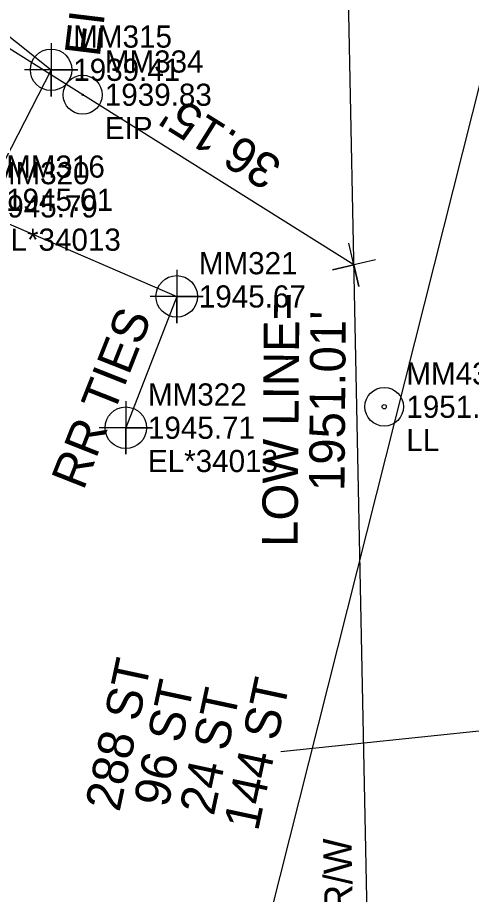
# Model space of a CAD drawing. Extents: x 1004514 to 1005247, y 553695 to 554706.
# Drawn here: x 1004934 to 1004985.3, y 554027.6 to 554126.5 of the extents above; entities that cross this region are included whole.
import ezdxf

# ---------------------------------------------------------------- set-up
doc = ezdxf.new("R2010")
doc.units = 0
for name, color, linetype in [('Default Symbol Cogo Comment', 7, 'Continuous'), ('Default Symbol Cogo Elevation', 7, 'Continuous'), ('Default Symbol Cogo Number', 7, 'Continuous'), ('Exist Building', 7, 'Continuous'), ('Exist Building Cogo Elevation', 7, 'Continuous'), ('Exist Building Cogo Number', 7, 'Continuous'), ('Exist Building Cogo Point CELL', 7, 'Continuous'), ('Exist Building Text', 7, 'Continuous'), ('Exist Property Corner CELL', 7, 'Continuous'), ('Exist Property Iron Pin CELL', 7, 'Continuous'), ('Exist Property Iron Pin Cogo Comment', 7, 'Continuous'), ('Exist Property Iron Pin Cogo Elevation', 7, 'Continuous'), ('Exist Property Iron Pin Cogo Number', 7, 'Continuous'), ('Exist Property Iron Pin Text', 7, 'Continuous'), ('Exist Property Line', 7, 'Continuous'), ('Exist Property Line Text', 7, 'Continuous'), ('Exist Right of Way Line', 7, 'Continuous'), ('Exist Right of Way Line Text', 7, 'Continuous'), ('Exist Utilities Other Located Object CELL', 7, 'Continuous'), ('Exist Utilities Other Located Object Text', 7, 'Continuous'), ('Exist Utilities Telephone UG Conduit SUE LOS B Leader', 7, 'Continuous'), ('Exist Utilities Telephone UG Conduit SUE LOS B Text', 7, 'Continuous'), ('Exist Vegetation Woods Line', 7, 'Continuous'), ('Exist Vegetation Woods Line Cogo Elevation', 7, 'Continuous'), ('Exist Vegetation Woods Line Cogo Number', 7, 'Continuous'), ('Exist Vegetation Woods Line Cogo Point CELL', 7, 'Continuous'), ('Scratch_Level_3', 7, 'Continuous')]:
    doc.layers.add(name, color=color, linetype=linetype)

msp = doc.modelspace()

# ---------------------------------------------------------------- linework, layer by layer
at = {"layer": 'Exist Building'}
msp.add_lwpolyline([(1004928.515, 554105.229), (1004952.008, 554095.071), (1004946.261, 554080.257)], dxfattribs=at)
at = {"layer": 'Exist Building Cogo Point CELL'}
for points in [[(1004952.008, 554098.071), (1004952.008, 554092.071), (1004952.008, 554095.071), (1004955.008, 554095.071), (1004949.008, 554095.071)], [(1004946.261, 554083.257), (1004946.261, 554077.257), (1004946.261, 554080.257), (1004949.261, 554080.257), (1004943.261, 554080.257)]]:
    msp.add_lwpolyline(points, dxfattribs=at)
for centre in [(1004952.008, 554095.071), (1004946.261, 554080.257)]:
    msp.add_circle(centre, 2.344, dxfattribs=at)
at = {"layer": 'Exist Property Corner CELL'}
msp.add_line((1004972.021, 554098.632), (1004972.021, 554098.632), dxfattribs=at)
msp.add_lwpolyline([(1004974.458, 554099.191), (1004969.584, 554098.072), (1004972.021, 554098.632), (1004972.58, 554096.195), (1004971.462, 554101.068)], dxfattribs=at)
at = {"layer": 'Exist Property Iron Pin CELL'}
for radius in [2.203, 0.0707]:
    msp.add_circle((1004941.389, 554117.826), radius, dxfattribs=at)
at = {"layer": 'Exist Property Line'}
for p, q in [((1004941.389, 554117.826), (1004781.385, 554218.083)), ((1004972.021, 554098.632), (1004941.389, 554117.826))]:
    msp.add_line(p, q, dxfattribs=at)
at = {"layer": 'Exist Right of Way Line'}
msp.add_line((1004974.633, 553969.453), (1004971.246, 554136.929), dxfattribs=at)
at = {"layer": 'Exist Utilities Other Located Object CELL'}
for radius in [2.18, 0.24]:
    msp.add_circle((1004975.438, 554082.623), radius, dxfattribs=at)
at = {"layer": 'Exist Utilities Telephone UG Conduit SUE LOS B Leader'}
msp.add_line((1004992.647, 554046.707), (1004963.772, 554043.71), dxfattribs=at)
at = {"layer": 'Exist Vegetation Woods Line'}
msp.add_lwpolyline([(1004918.605, 554135.996), (1004937.826, 554120.641), (1004930.248, 554105.974), (1004908.277, 554113.327)], dxfattribs=at)
at = {"layer": 'Exist Vegetation Woods Line Cogo Point CELL'}
msp.add_lwpolyline([(1004937.826, 554123.641), (1004937.826, 554117.641), (1004937.826, 554120.641), (1004940.826, 554120.641), (1004934.826, 554120.641)], dxfattribs=at)
msp.add_circle((1004937.826, 554120.641), 2.344, dxfattribs=at)
at = {"layer": 'Scratch_Level_3'}
msp.add_line((1004952.617, 553985.711), (1005030.054, 554292.752), dxfattribs=at)

# ---------------------------------------------------------------- texts
at = {"layer": 'Default Symbol Cogo Comment'}
msp.add_text('LL', height=2.5, dxfattribs=at).set_placement((1004977.938, 554077.623))
at = {"layer": 'Default Symbol Cogo Elevation'}
msp.add_text('1951.01', height=2.5, dxfattribs=at).set_placement((1004977.938, 554081.373))
at = {"layer": 'Default Symbol Cogo Number'}
msp.add_text('MM438', height=2.5, dxfattribs=at).set_placement((1004977.938, 554085.123))
at = {"layer": 'Exist Building Cogo Elevation'}
for s, p in [('1945.79', (1004931.015, 554103.979)), ('BL*34013', (1004931.015, 554100.229)), ('1945.67', (1004954.508, 554093.821)), ('1945.71', (1004948.761, 554079.007)), ('EL*34013', (1004948.761, 554075.257))]:
    msp.add_text(s, height=2.5, dxfattribs=at).set_placement(p)
at = {"layer": 'Exist Building Cogo Number'}
for s, p in [('MM320', (1004931.015, 554107.729)), ('MM321', (1004954.508, 554097.571)), ('MM322', (1004948.761, 554082.757))]:
    msp.add_text(s, height=2.5, dxfattribs=at).set_placement(p)
at = {"layer": 'Exist Building Text'}
msp.add_text('RR TIES', height=4, rotation=68.45312, dxfattribs=at).set_placement((1004941.469, 554073.091))
at = {"layer": 'Exist Property Iron Pin Cogo Comment'}
msp.add_text('EIP', height=2.5, dxfattribs=at).set_placement((1004943.889, 554112.826))
at = {"layer": 'Exist Property Iron Pin Cogo Elevation'}
msp.add_text('1939.83', height=2.5, dxfattribs=at).set_placement((1004943.889, 554116.576))
at = {"layer": 'Exist Property Iron Pin Cogo Number'}
msp.add_text('MM334', height=2.5, dxfattribs=at).set_placement((1004943.889, 554120.326))
at = {"layer": 'Exist Property Iron Pin Text'}
msp.add_text('EIP', height=4, rotation=83.04421, dxfattribs=at).set_placement((1004943.308, 554121.998))
at = {"layer": 'Exist Property Line Text'}
msp.add_text("36.15'", height=4, rotation=147.92897, dxfattribs=at).set_placement((1004964.135, 554110.277))
at = {"layer": 'Exist Right of Way Line Text'}
msp.add_text('EXISTING R/W', height=3.2, rotation=91.15854, dxfattribs=at).set_placement((1004972.324, 554004.502))
at = {"layer": 'Exist Utilities Other Located Object Text'}
for s, p in [('LOW LINE=', (1004965.648, 554066.799)), ("1951.01'", (1004970.948, 554073.088))]:
    msp.add_text(s, height=4, rotation=89.54695, dxfattribs=at).set_placement(p)
at = {"layer": 'Exist Utilities Telephone UG Conduit SUE LOS B Text'}
for s, p in [('288 ST', (1004945.543, 554036.817)), ('96 ST', (1004951.013, 554037.29)), ('144 ST', (1004961.181, 554034.631)), ('24 ST', (1004956.186, 554036.376))]:
    msp.add_text(s, height=4, rotation=77.92226, dxfattribs=at).set_placement(p)
at = {"layer": 'Exist Vegetation Woods Line Cogo Elevation'}
for s, p in [('1939.41', (1004940.326, 554119.391)), ('1945.01', (1004932.748, 554104.724))]:
    msp.add_text(s, height=2.5, dxfattribs=at).set_placement(p)
at = {"layer": 'Exist Vegetation Woods Line Cogo Number'}
for s, p in [('MM315', (1004940.326, 554123.141)), ('MM316', (1004932.748, 554108.474))]:
    msp.add_text(s, height=2.5, dxfattribs=at).set_placement(p)

doc.saveas('drawing.dxf')
